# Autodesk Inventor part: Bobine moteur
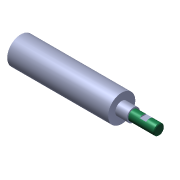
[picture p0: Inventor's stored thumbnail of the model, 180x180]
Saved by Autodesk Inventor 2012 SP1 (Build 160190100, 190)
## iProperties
Created: 2014-12
Part Number: Bobine moteur
Material: Default
Document SubType Name: Modeling
Designer: Bruno
Density: 1 g/cm^3
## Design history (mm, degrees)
node "Bobine moteur1"
node "Bobine moteur"
node "Base1"
